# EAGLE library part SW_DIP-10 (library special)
DIP SWITCH
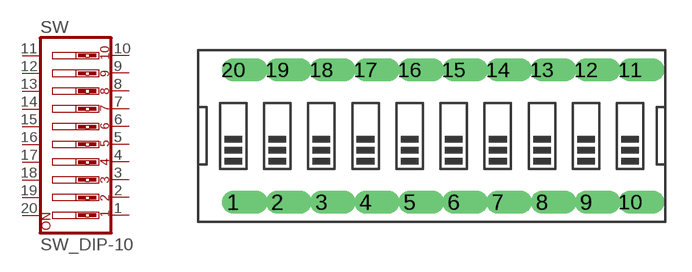
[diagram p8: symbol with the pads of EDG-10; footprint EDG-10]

Designator prefix SW

## SW_DIP-10  [EDG-10]
1  1  pas
2  2  pas
3  3  pas
4  4  pas
5  5  pas
6  6  pas
7  7  pas
8  8  pas
9  9  pas
10  10  pas
11  11  pas
12  12  pas
13  13  pas
14  14  pas
15  15  pas
16  16  pas
17  17  pas
18  18  pas
19  19  pas
20  20  pas

## Footprint EDG-10 (pad centres in mm)
DIP SWITCH
drill 0.813 offset: 1 -11.43,-3.81; 2 -8.89,-3.81; 3 -6.35,-3.81; 4 -3.81,-3.81; 5 -1.27,-3.81; 6 1.27,-3.81; 7 3.81,-3.81; 8 6.35,-3.81; 9 8.89,-3.81; 10 11.43,-3.81; 11 11.43,3.81; 12 8.89,3.81; 13 6.35,3.81; 14 3.81,3.81; 15 1.27,3.81; 16 -1.27,3.81; 17 -3.81,3.81; 18 -6.35,3.81; 19 -8.89,3.81; 20 -11.43,3.81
